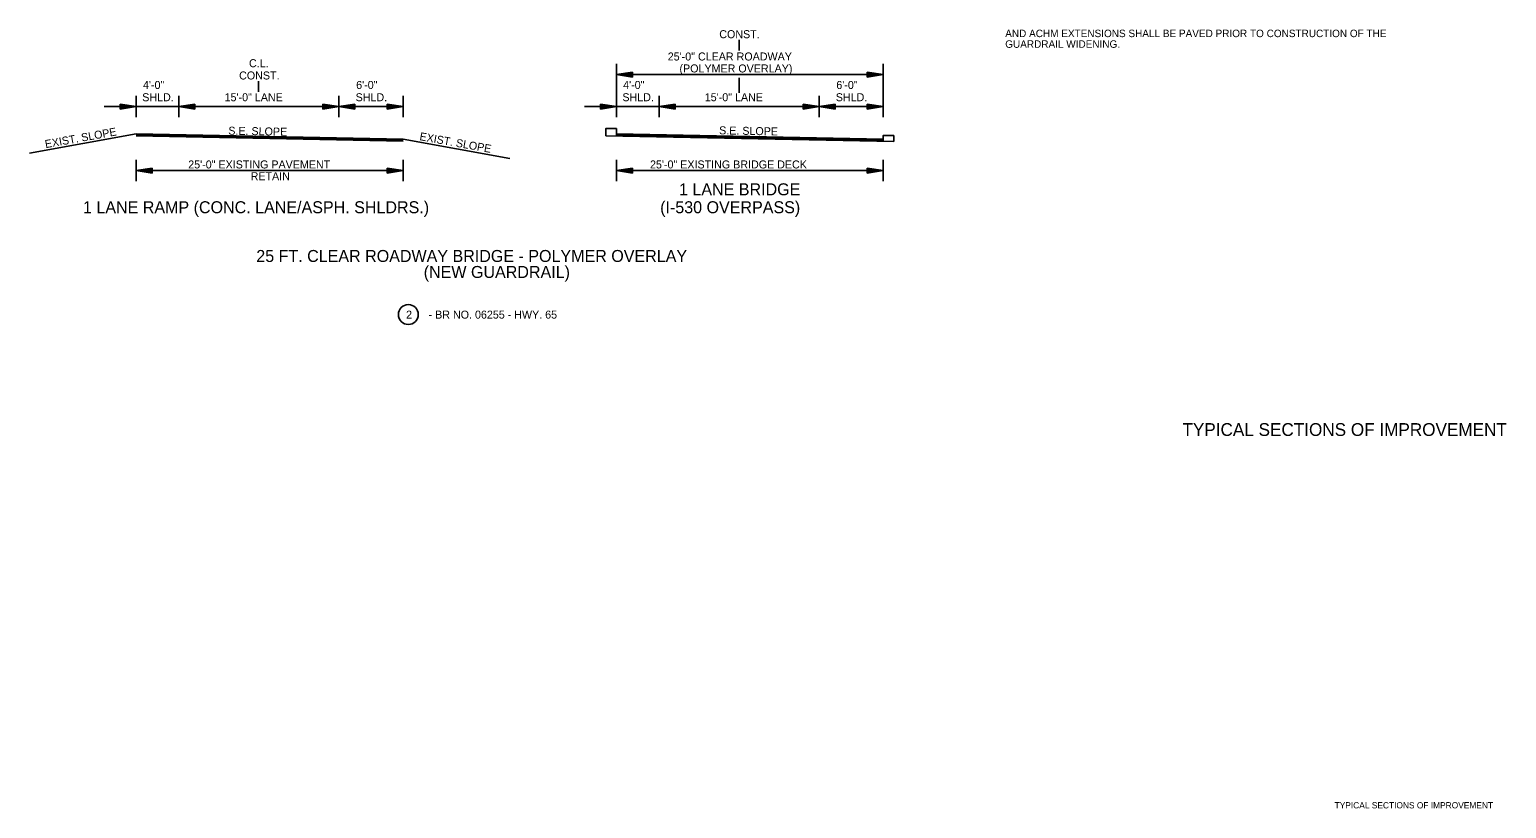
# Model space of a CAD drawing. Extents: x 545241 to 1930787, y -1971772 to 596640.
# Drawn here: x 546884 to 548268, y -1948692 to -1947962 of the extents above; entities that cross this region are included whole.
import ezdxf

# ---------------------------------------------------------------- set-up
doc = ezdxf.new("R2010")
doc.units = 0
for name, color, linetype in [('R_Border', 7, 'Continuous'), ('R_Border Notes', 7, 'Continuous'), ('R_Border Prem', 7, 'Continuous')]:
    doc.layers.add(name, color=color, linetype=linetype)

msp = doc.modelspace()

# ---------------------------------------------------------------- linework, layer by layer
at = {"layer": 'R_Border'}
for p, q in [((547548.7, -1947971.4), (547548.7, -1947981.4)), ((547433.7, -1947994), (547433.7, -1948044)), ((547448.7, -1948001.8), (547433.7, -1948004)), ((547448.7, -1948002.2), (547436.2, -1948004)), ((547448.7, -1948002.5), (547438.8, -1948004)), ((547448.7, -1948002.9), (547441.3, -1948004)), ((547448.7, -1948006.3), (547448.7, -1948001.8)), ((547668.7, -1948001.8), (547683.7, -1948004)), ((547668.7, -1948001.8), (547668.7, -1948006.3)), ((547668.7, -1948002.2), (547681.2, -1948004)), ((547668.7, -1948002.5), (547678.6, -1948004)), ((547668.7, -1948002.9), (547676.1, -1948004)), ((547683.7, -1947994), (547683.7, -1948044)), ((547433.7, -1948004), (547683.7, -1948004)), ((547448.7, -1948006.3), (547433.7, -1948004)), ((547448.7, -1948005.9), (547436.2, -1948004)), ((547448.7, -1948005.5), (547438.8, -1948004)), ((547448.7, -1948005.2), (547441.3, -1948004)), ((547448.7, -1948003.3), (547443.8, -1948004)), ((547448.7, -1948004.8), (547443.8, -1948004)), ((547448.7, -1948003.7), (547446.3, -1948004)), ((547448.7, -1948004.4), (547446.3, -1948004)), ((547548.7, -1948007), (547548.7, -1948021)), ((547668.7, -1948003.3), (547673.6, -1948004)), ((547668.7, -1948003.7), (547671.1, -1948004)), ((547668.7, -1948006.3), (547683.7, -1948004)), ((547668.7, -1948004.8), (547673.6, -1948004)), ((547668.7, -1948005.5), (547678.6, -1948004)), ((547668.7, -1948005.9), (547681.2, -1948004)), ((547668.7, -1948005.2), (547676.1, -1948004)), ((547668.7, -1948004.4), (547671.1, -1948004)), ((546983.7, -1948024), (546983.7, -1948044)), ((547023.7, -1948024), (547023.7, -1948044)), ((547173.7, -1948024), (547173.7, -1948044)), ((547233.7, -1948024), (547233.7, -1948044)), ((547473.7, -1948024), (547473.7, -1948044)), ((547623.7, -1948024), (547623.7, -1948044)), ((546953.7, -1948034), (547233.7, -1948034)), ((546968.7, -1948031.8), (546983.7, -1948034)), ((546968.7, -1948031.8), (546968.7, -1948036.3)), ((546968.7, -1948032.2), (546981.2, -1948034)), ((546968.7, -1948032.5), (546978.6, -1948034)), ((546968.7, -1948032.9), (546976.1, -1948034)), ((546968.7, -1948033.3), (546973.6, -1948034)), ((546968.7, -1948033.7), (546971.1, -1948034)), ((546968.7, -1948036.3), (546983.7, -1948034)), ((546968.7, -1948034.8), (546973.6, -1948034)), ((546968.7, -1948035.5), (546978.6, -1948034)), ((546968.7, -1948035.9), (546981.2, -1948034)), ((546968.7, -1948035.2), (546976.1, -1948034)), ((546968.7, -1948034.4), (546971.1, -1948034)), ((547038.7, -1948031.8), (547023.7, -1948034)), ((547038.7, -1948036.3), (547023.7, -1948034)), ((547038.7, -1948032.2), (547026.2, -1948034)), ((547038.7, -1948035.9), (547026.2, -1948034)), ((547038.7, -1948032.5), (547028.8, -1948034)), ((547038.7, -1948035.5), (547028.8, -1948034)), ((547038.7, -1948032.9), (547031.3, -1948034)), ((547038.7, -1948035.2), (547031.3, -1948034)), ((547038.7, -1948033.3), (547033.8, -1948034)), ((547038.7, -1948034.8), (547033.8, -1948034)), ((547038.7, -1948033.7), (547036.3, -1948034)), ((547038.7, -1948034.4), (547036.3, -1948034)), ((547038.7, -1948036.3), (547038.7, -1948031.8)), ((547158.7, -1948031.8), (547173.7, -1948034)), ((547158.7, -1948031.8), (547158.7, -1948036.3)), ((547158.7, -1948032.2), (547171.2, -1948034)), ((547158.7, -1948032.5), (547168.6, -1948034)), ((547158.7, -1948032.9), (547166.1, -1948034)), ((547158.7, -1948033.3), (547163.6, -1948034)), ((547158.7, -1948033.7), (547161.1, -1948034)), ((547158.7, -1948036.3), (547173.7, -1948034)), ((547158.7, -1948034.8), (547163.6, -1948034)), ((547158.7, -1948035.5), (547168.6, -1948034)), ((547158.7, -1948035.9), (547171.2, -1948034)), ((547158.7, -1948035.2), (547166.1, -1948034)), ((547158.7, -1948034.4), (547161.1, -1948034)), ((547188.7, -1948031.8), (547173.7, -1948034)), ((547188.7, -1948036.3), (547173.7, -1948034)), ((547188.7, -1948032.2), (547176.2, -1948034)), ((547188.7, -1948035.9), (547176.2, -1948034)), ((547188.7, -1948032.5), (547178.8, -1948034)), ((547188.7, -1948035.5), (547178.8, -1948034)), ((547188.7, -1948032.9), (547181.3, -1948034)), ((547188.7, -1948035.2), (547181.3, -1948034)), ((547188.7, -1948033.3), (547183.8, -1948034)), ((547188.7, -1948034.8), (547183.8, -1948034)), ((547188.7, -1948033.7), (547186.3, -1948034)), ((547188.7, -1948034.4), (547186.3, -1948034)), ((547188.7, -1948036.3), (547188.7, -1948031.8)), ((547218.7, -1948031.8), (547233.7, -1948034)), ((547218.7, -1948031.8), (547218.7, -1948036.3)), ((547218.7, -1948032.2), (547231.2, -1948034)), ((547218.7, -1948032.5), (547228.6, -1948034)), ((547218.7, -1948032.9), (547226.1, -1948034)), ((547218.7, -1948033.3), (547223.6, -1948034)), ((547218.7, -1948033.7), (547221.1, -1948034)), ((547218.7, -1948036.3), (547233.7, -1948034)), ((547218.7, -1948034.8), (547223.6, -1948034)), ((547218.7, -1948035.5), (547228.6, -1948034)), ((547218.7, -1948035.9), (547231.2, -1948034)), ((547218.7, -1948035.2), (547226.1, -1948034)), ((547218.7, -1948034.4), (547221.1, -1948034)), ((547403.7, -1948034), (547683.7, -1948034)), ((547418.7, -1948031.8), (547433.7, -1948034)), ((547418.7, -1948031.8), (547418.7, -1948036.3)), ((547418.7, -1948032.2), (547431.2, -1948034)), ((547418.7, -1948032.5), (547428.6, -1948034)), ((547418.7, -1948032.9), (547426.1, -1948034)), ((547418.7, -1948033.3), (547423.6, -1948034)), ((547418.7, -1948033.7), (547421.1, -1948034)), ((547418.7, -1948036.3), (547433.7, -1948034)), ((547418.7, -1948034.8), (547423.6, -1948034)), ((547418.7, -1948035.5), (547428.6, -1948034)), ((547418.7, -1948035.9), (547431.2, -1948034)), ((547418.7, -1948035.2), (547426.1, -1948034)), ((547418.7, -1948034.4), (547421.1, -1948034)), ((547488.7, -1948031.8), (547473.7, -1948034)), ((547488.7, -1948036.3), (547473.7, -1948034)), ((547488.7, -1948032.2), (547476.2, -1948034)), ((547488.7, -1948035.9), (547476.2, -1948034)), ((547488.7, -1948032.5), (547478.8, -1948034)), ((547488.7, -1948035.5), (547478.8, -1948034)), ((547488.7, -1948032.9), (547481.3, -1948034)), ((547488.7, -1948035.2), (547481.3, -1948034)), ((547488.7, -1948033.3), (547483.8, -1948034)), ((547488.7, -1948034.8), (547483.8, -1948034)), ((547488.7, -1948033.7), (547486.3, -1948034)), ((547488.7, -1948034.4), (547486.3, -1948034)), ((547488.7, -1948036.3), (547488.7, -1948031.8)), ((547608.7, -1948031.8), (547623.7, -1948034)), ((547608.7, -1948031.8), (547608.7, -1948036.3)), ((547608.7, -1948032.2), (547621.2, -1948034)), ((547608.7, -1948032.5), (547618.6, -1948034)), ((547608.7, -1948032.9), (547616.1, -1948034)), ((547608.7, -1948033.3), (547613.6, -1948034)), ((547608.7, -1948033.7), (547611.1, -1948034)), ((547608.7, -1948036.3), (547623.7, -1948034)), ((547608.7, -1948034.8), (547613.6, -1948034)), ((547608.7, -1948035.5), (547618.6, -1948034)), ((547608.7, -1948035.9), (547621.2, -1948034)), ((547608.7, -1948035.2), (547616.1, -1948034)), ((547608.7, -1948034.4), (547611.1, -1948034)), ((547638.7, -1948031.8), (547623.7, -1948034)), ((547638.7, -1948036.3), (547623.7, -1948034)), ((547638.7, -1948032.2), (547626.2, -1948034)), ((547638.7, -1948035.9), (547626.2, -1948034)), ((547638.7, -1948032.5), (547628.8, -1948034)), ((547638.7, -1948035.5), (547628.8, -1948034)), ((547638.7, -1948032.9), (547631.3, -1948034)), ((547638.7, -1948035.2), (547631.3, -1948034)), ((547638.7, -1948033.3), (547633.8, -1948034)), ((547638.7, -1948034.8), (547633.8, -1948034)), ((547638.7, -1948033.7), (547636.3, -1948034)), ((547638.7, -1948034.4), (547636.3, -1948034)), ((547638.7, -1948036.3), (547638.7, -1948031.8)), ((547668.7, -1948031.8), (547683.7, -1948034)), ((547668.7, -1948031.8), (547668.7, -1948036.3)), ((547668.7, -1948032.2), (547681.2, -1948034)), ((547668.7, -1948032.5), (547678.6, -1948034)), ((547668.7, -1948032.9), (547676.1, -1948034)), ((547668.7, -1948033.3), (547673.6, -1948034)), ((547668.7, -1948033.7), (547671.1, -1948034)), ((547668.7, -1948036.3), (547683.7, -1948034)), ((547668.7, -1948034.8), (547673.6, -1948034)), ((547668.7, -1948035.5), (547678.6, -1948034)), ((547668.7, -1948035.9), (547681.2, -1948034)), ((547668.7, -1948035.2), (547676.1, -1948034)), ((547668.7, -1948034.4), (547671.1, -1948034)), ((546983.7, -1948059.7), (546883.7, -1948077.7)), ((546983.7, -1948059.7), (547233.7, -1948064.7)), ((546983.7, -1948060), (547233.7, -1948065)), ((546983.7, -1948060.3), (547233.7, -1948065.3)), ((546983.7, -1948060.6), (547233.7, -1948065.6)), ((546983.7, -1948060.9), (547233.7, -1948065.9)), ((546983.7, -1948061.2), (547233.7, -1948066.2)), ((546983.7, -1948061.5), (547233.7, -1948066.5)), ((547233.7, -1948064.7), (547333.7, -1948082.7)), ((547423.7, -1948061.3), (547693.7, -1948066.7)), ((547433.7, -1948059.7), (547683.7, -1948064.7)), ((547433.7, -1948060), (547683.7, -1948065)), ((547433.7, -1948060.3), (547683.7, -1948065.3)), ((547433.7, -1948060.6), (547683.7, -1948065.6)), ((547433.7, -1948060.9), (547683.7, -1948065.9)), ((547433.7, -1948061.2), (547683.7, -1948066.2)), ((546983.7, -1948084), (546983.7, -1948104)), ((547233.7, -1948084), (547233.7, -1948104)), ((547433.7, -1948084), (547433.7, -1948104)), ((547683.7, -1948084), (547683.7, -1948104)), ((546998.7, -1948091.8), (546983.7, -1948094)), ((546983.7, -1948094), (547233.7, -1948094)), ((546998.7, -1948096.3), (546983.7, -1948094)), ((546998.7, -1948092.2), (546986.2, -1948094)), ((546998.7, -1948095.9), (546986.2, -1948094)), ((546998.7, -1948092.5), (546988.8, -1948094)), ((546998.7, -1948095.5), (546988.8, -1948094)), ((546998.7, -1948092.9), (546991.3, -1948094)), ((546998.7, -1948095.2), (546991.3, -1948094)), ((546998.7, -1948093.3), (546993.8, -1948094)), ((546998.7, -1948094.8), (546993.8, -1948094)), ((546998.7, -1948093.7), (546996.3, -1948094)), ((546998.7, -1948094.4), (546996.3, -1948094)), ((546998.7, -1948096.3), (546998.7, -1948091.8)), ((547218.7, -1948091.8), (547233.7, -1948094)), ((547218.7, -1948091.8), (547218.7, -1948096.3)), ((547218.7, -1948092.2), (547231.2, -1948094)), ((547218.7, -1948092.5), (547228.6, -1948094)), ((547218.7, -1948092.9), (547226.1, -1948094)), ((547218.7, -1948093.3), (547223.6, -1948094)), ((547218.7, -1948093.7), (547221.1, -1948094)), ((547218.7, -1948096.3), (547233.7, -1948094)), ((547218.7, -1948094.8), (547223.6, -1948094)), ((547218.7, -1948095.5), (547228.6, -1948094)), ((547218.7, -1948095.9), (547231.2, -1948094)), ((547218.7, -1948095.2), (547226.1, -1948094)), ((547218.7, -1948094.4), (547221.1, -1948094)), ((547448.7, -1948091.8), (547433.7, -1948094)), ((547433.7, -1948094), (547683.7, -1948094)), ((547448.7, -1948096.3), (547433.7, -1948094)), ((547448.7, -1948092.2), (547436.2, -1948094)), ((547448.7, -1948095.9), (547436.2, -1948094)), ((547448.7, -1948092.5), (547438.8, -1948094)), ((547448.7, -1948095.5), (547438.8, -1948094)), ((547448.7, -1948092.9), (547441.3, -1948094)), ((547448.7, -1948095.2), (547441.3, -1948094)), ((547448.7, -1948093.3), (547443.8, -1948094)), ((547448.7, -1948094.8), (547443.8, -1948094)), ((547448.7, -1948093.7), (547446.3, -1948094)), ((547448.7, -1948094.4), (547446.3, -1948094)), ((547448.7, -1948096.3), (547448.7, -1948091.8)), ((547668.7, -1948091.8), (547683.7, -1948094)), ((547668.7, -1948091.8), (547668.7, -1948096.3)), ((547668.7, -1948092.2), (547681.2, -1948094)), ((547668.7, -1948092.5), (547678.6, -1948094)), ((547668.7, -1948092.9), (547676.1, -1948094)), ((547668.7, -1948093.3), (547673.6, -1948094)), ((547668.7, -1948093.7), (547671.1, -1948094)), ((547668.7, -1948096.3), (547683.7, -1948094)), ((547668.7, -1948094.8), (547673.6, -1948094)), ((547668.7, -1948095.5), (547678.6, -1948094)), ((547668.7, -1948095.9), (547681.2, -1948094)), ((547668.7, -1948095.2), (547676.1, -1948094)), ((547668.7, -1948094.4), (547671.1, -1948094))]:
    msp.add_line(p, q, dxfattribs=at)
for points in [[(547098.4, -1948020.1), (547098.4, -1948010.1)], [(547433.7, -1948061.2), (547433.7, -1948054.7), (547423.7, -1948054.7), (547423.7, -1948061.3)], [(546983.7, -1948059.7), (547023.7, -1948060.5), (547098.7, -1948062), (547173.7, -1948063.5), (547233.7, -1948064.7)], [(547433.7, -1948059.7), (547473.7, -1948060.5), (547548.7, -1948062), (547623.7, -1948063.5), (547683.7, -1948064.7)], [(547683.7, -1948066.2), (547683.7, -1948061.2), (547693.7, -1948061.2), (547693.7, -1948066.7)]]:
    msp.add_lwpolyline(points, dxfattribs=at)
msp.add_circle((547238.7, -1948229), 9.34, dxfattribs=at)

# ---------------------------------------------------------------- texts
for s, height, p in [('CONST.', 7.5, (547530.1, -1947969.9)), ('25\'-0" CLEAR ROADWAY', 7.5, (547481.8, -1947990.8)), ('CONST.', 7.5, (547080.1, -1948008.6)), ('C.L.', 7.5, (547089.4, -1947997.1)), ('(POLYMER OVERLAY)', 7.5, (547492.8, -1948002)), ('4\'-0"', 7.5, (546990, -1948017.5)), ('6\'-0"', 7.5, (547189.8, -1948017.5)), ('4\'-0"', 7.5, (547440, -1948017.5)), ('6\'-0"', 7.5, (547639.8, -1948017.5)), ('SHLD.', 7.5, (546989.3, -1948029)), ('15\'-0" LANE', 7.5, (547066.5, -1948029)), ('SHLD.', 7.5, (547189.3, -1948029)), ('SHLD.', 7.5, (547439.3, -1948029)), ('15\'-0" LANE', 7.5, (547516.5, -1948029)), ('SHLD.', 7.5, (547639.3, -1948029)), ('25\'-0" EXISTING PAVEMENT', 7.5, (547032.4, -1948092)), ('25\'-0" EXISTING BRIDGE DECK', 7.5, (547465.2, -1948092)), ('RETAIN', 7.5, (547090.9, -1948103)), ('1 LANE BRIDGE', 11.25, (547492.4, -1948117.2)), ('1 LANE RAMP (CONC. LANE/ASPH. SHLDRS.)', 11.25, (546933.8, -1948134)), ('(I-530 OVERPASS)', 11.25, (547474.7, -1948134)), ('25 FT. CLEAR ROADWAY BRIDGE - POLYMER OVERLAY', 11.25, (547096.2, -1948179.7)), ('(NEW GUARDRAIL)', 11.25, (547253.1, -1948194.7)), ('2', 7.5, (547236.6, -1948232.8)), ('- BR NO. 06255 - HWY. 65', 7.5, (547257.7, -1948232.8))]:
    msp.add_text(s, height=height, dxfattribs=at).set_placement(p)
for s, height, rotation, p in [('EXIST. SLOPE', 7.5, 10.204, (546898.8, -1948073)), ('S.E. SLOPE', 7.5, 358.8542, (547069.9, -1948060.3)), ('EXIST. SLOPE', 7.5, 349.796, (547248.8, -1948065.4)), ('S.E. SLOPE', 7.5, 358.8542, (547529.9, -1948060)), ('TYPICAL SECTIONS OF IMPROVEMENT', 12, 360, (547964.2, -1948342.8))]:
    msp.add_text(s, height=height, rotation=rotation, dxfattribs=at).set_placement(p)
at = {"layer": 'R_Border Notes'}
for s, p in [('    AND ACHM EXTENSIONS SHALL BE PAVED PRIOR TO CONSTRUCTION OF THE', (547787.7, -1947968.9)), ('    GUARDRAIL WIDENING.', (547787.7, -1947978.9))]:
    msp.add_text(s, height=7, dxfattribs=at).set_placement(p)
at = {"layer": 'R_Border Prem'}
msp.add_text('TYPICAL SECTIONS OF IMPROVEMENT', height=5.862, rotation=360, dxfattribs=at).set_placement((548106.8, -1948692))

doc.saveas('drawing.dxf')
